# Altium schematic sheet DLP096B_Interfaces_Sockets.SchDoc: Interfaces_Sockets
size 431 x 279 mm; Date: Not shown in title block; ApprovedBy: Not shown in title block; CheckedBy: Not shown in title block; Author: Not shown in title block; CompanyName: Not shown in title block; Engineer: Not shown in title block; Organization: Not shown in title block; Address1: Not shown in title block; Address2: Not shown in title block; Address3: Not shown in title block; Address4: Not shown in title block; DocumentNumber: 8; Revision: Use project parameter SCH_Rev; SheetNumber: 8; SheetTotal: 10; PageSetup: Record=PageOptions¦CenterHorizontal=True¦CenterVertical=True¦PrintScale=1.00¦XCorrection=1.00¦YCorrection=1.00¦PrintKind=0¦BorderSize=5000000¦LeftOffset=0¦BottomOffset=0¦Orientation=2¦PaperLength=1000¦PaperWidth=1000¦Scale=100¦PaperSource=15¦PrintQuality=600¦MediaType=1¦DitherType=10¦PaperKind=Letter¦PrintScaleMode=1
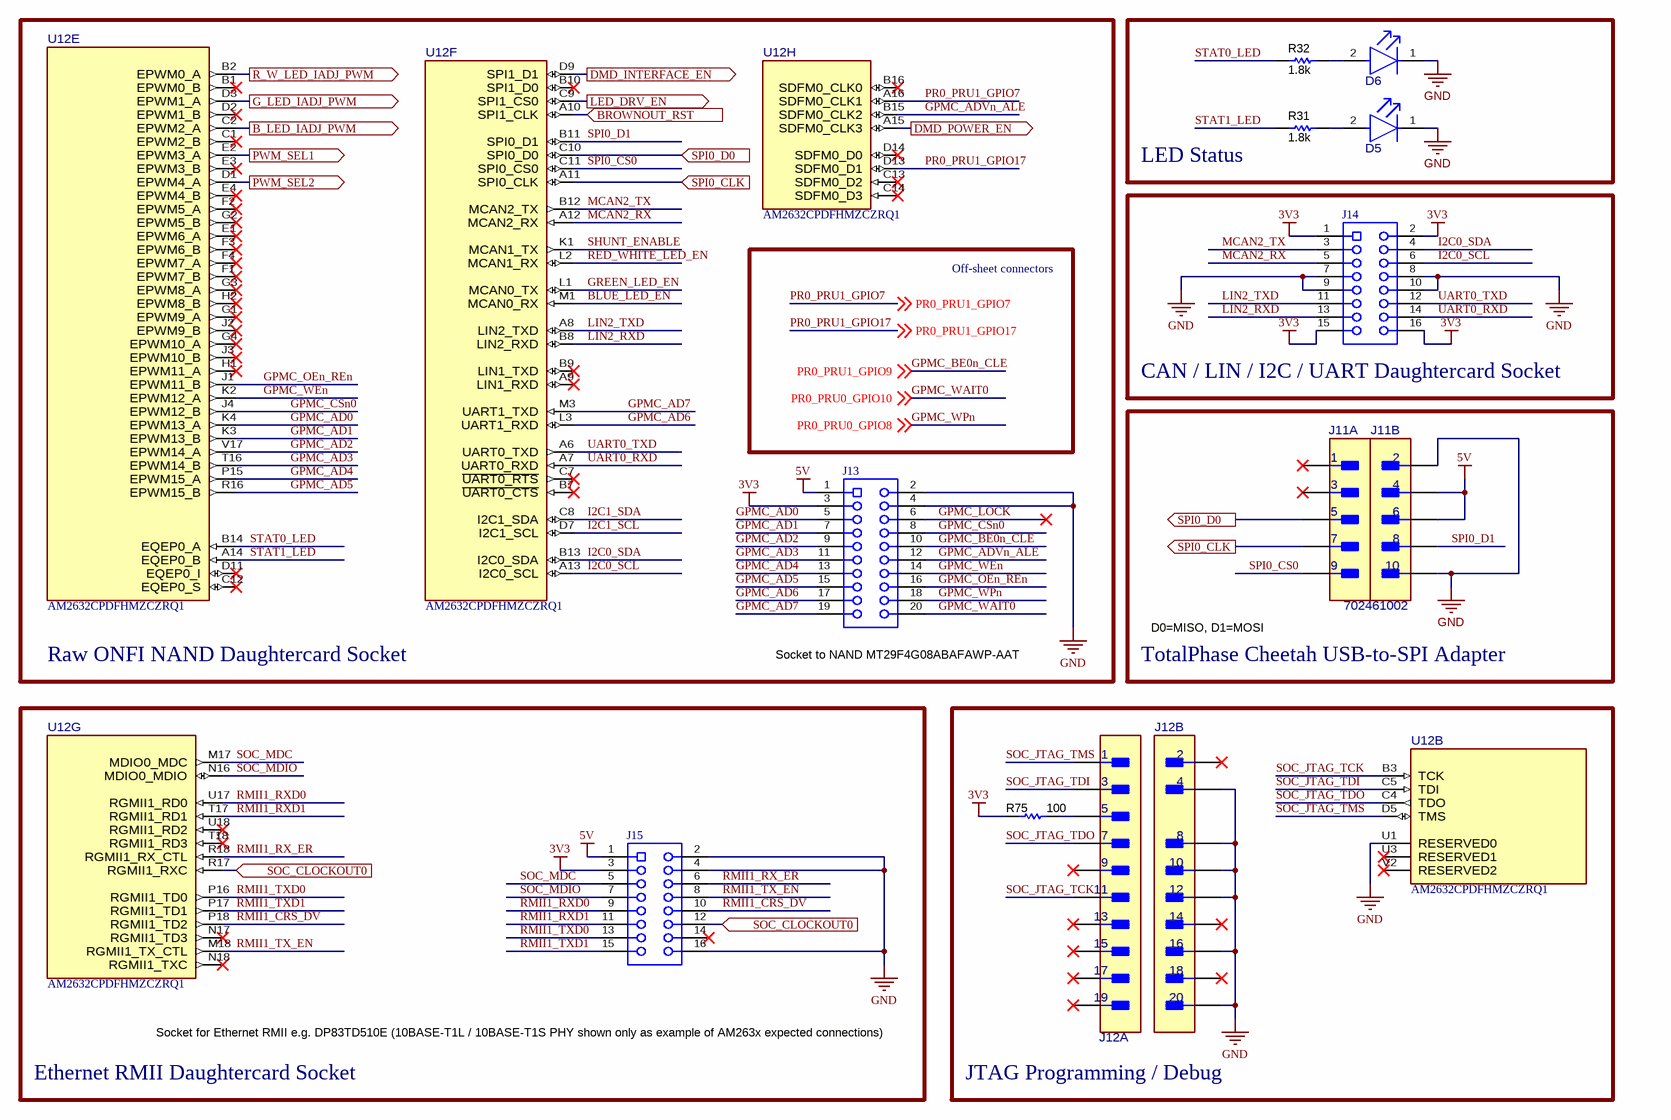
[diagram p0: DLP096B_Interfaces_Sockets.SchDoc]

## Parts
D5  LSL29K-G1H2-1-Z  [FP-LSL29K-G1H2-1-Z_0603-0]  (value not drawn)
D6  LSL29K-G1H2-1-Z  [FP-LSL29K-G1H2-1-Z_0603-0]  (value not drawn)
J11  702461002  [FP-702461002_HDR10-MFG]  (value not drawn)  (parts A,B of 2)
J12  FTR-110-03-G-D-06  [FP-FTR-110-03-G-D-06_HDR19-MFG]  (value not drawn)  (parts A,B of 2)
J13  RSM-110-02-L-D  [Samtec_RSM-110-02-x-D]  (value not drawn)
J14  FLE-108-01-G-DV-A  [Samtec_FLE-108-01-x-DV-A]  (value not drawn)
J15  FLE-108-01-G-DV-A  [Samtec_FLE-108-01-x-DV-A]  (value not drawn)
R31  ValueDisplayed: 1.8k  [0402L]  (hidden comment: CRCW04021K80JNED)
R32  ValueDisplayed: 1.8k  [0402L]  (hidden comment: CRCW04021K80JNED)
R75  ValueDisplayed: 100  [0402L]  (hidden comment: ERJ-2GEJ101X)
U12  PartNumber: AM2632CPDFHMZCZRQ1  [ZCZ0324A-MFG]  (hidden comment: XAM2634AOLFGMZCZQ)  (parts B,E,F,G,H of 13)

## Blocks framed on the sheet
Raw ONFI NAND Daughtercard Socket: J13 U12
LED Status: D5 D6 R31 R32
CAN / LIN / I2C / UART Daughtercard Socket: J14
TotalPhase Cheetah USB-to-SPI Adapter: J11
Ethernet RMII Daughtercard Socket: J15 U12
JTAG Programming / Debug: J12 R75 U12

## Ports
B_LED_IADJ_PWM (out), BROWNOUT_RST (in), DMD_INTERFACE_EN (out), DMD_POWER_EN (out), G_LED_IADJ_PWM (out), LED_DRV_EN (out), PWM_SEL1 (out), PWM_SEL2 (out), R_W_LED_IADJ_PWM (out), SOC_CLOCKOUT0 (in), SPI0_CLK (in), SPI0_CLK (out), SPI0_D0 (in), SPI0_D0 (out)

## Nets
3V3: J13.3 J14.1 J14.2 J14.15 J14.16 J15.3 R75.1
5V: J11.4 J11.6 J13.1 J15.1
GND: D5.1(CATHODE) D6.1(CATHODE) J11.2 J11.10 J12.4 J12.8 J12.10 J12.12 J12.16 J12.20 J13.2 J13.4 J14.7 J14.8 J14.9 J14.10 J15.2 J15.4 J15.16 U12.U1(RESERVED0)
B_LED_IADJ_PWM: U12.C2(EPWM2_A) ; port B_LED_IADJ_PWM
BLUE_LED_EN: U12.M1(MCAN0_RX)
BROWNOUT_RST: U12.A10(SPI1_CLK) ; port BROWNOUT_RST
DMD_INTERFACE_EN: U12.D9(SPI1_D1) ; port DMD_INTERFACE_EN
DMD_POWER_EN: U12.A15(SDFM0_CLK3) ; port DMD_POWER_EN
G_LED_IADJ_PWM: U12.D3(EPWM1_A) ; port G_LED_IADJ_PWM
GPMC_AD0: J13.5 U12.K4(EPWM13_A)
GPMC_AD1: J13.7 U12.K3(EPWM13_B)
GPMC_AD2: J13.9 U12.V17(EPWM14_A)
GPMC_AD3: J13.11 U12.T16(EPWM14_B)
GPMC_AD4: J13.13 U12.P15(EPWM15_A)
GPMC_AD5: J13.15 U12.R16(EPWM15_B)
GPMC_AD6: J13.17 U12.L3(UART1_RXD)
GPMC_AD7: J13.19 U12.M3(UART1_TXD)
GPMC_ADVn_ALE: J13.12 U12.B15(SDFM0_CLK2)
GPMC_BE0n_CLE: J13.10 ; off-sheet PR0_PRU1_GPIO9  [also labelled PR0_PRU1_GPIO9]
GPMC_CSn0: J13.8 U12.J4(EPWM12_B)
GPMC_LOCK: J13.6
GPMC_OEn_REn: J13.16 U12.J1(EPWM11_B)
GPMC_WAIT0: J13.20 ; off-sheet PR0_PRU0_GPIO10  [also labelled PR0_PRU0_GPIO10]
GPMC_WEn: J13.14 U12.K2(EPWM12_A)
GPMC_WPn: J13.18 ; off-sheet PR0_PRU0_GPIO8  [also labelled PR0_PRU0_GPIO8]
GREEN_LED_EN: U12.L1(MCAN0_TX)
I2C0_SCL: J14.6 U12.A13(I2C0_SCL)
I2C0_SDA: J14.4 U12.B13(I2C0_SDA)
I2C1_SCL: U12.D7(I2C1_SCL)
I2C1_SDA: U12.C8(I2C1_SDA)
LED_DRV_EN: U12.C9(SPI1_CS0) ; port LED_DRV_EN
LIN2_RXD: J14.13 U12.B8(LIN2_RXD)
LIN2_TXD: J14.11 U12.A8(LIN2_TXD)
MCAN2_RX: J14.5 U12.A12(MCAN2_RX)
MCAN2_TX: J14.3 U12.B12(MCAN2_TX)
PR0_PRU1_GPIO7: U12.A16(SDFM0_CLK1) ; off-sheet PR0_PRU1_GPIO7
PR0_PRU1_GPIO17: U12.D13(SDFM0_D1) ; off-sheet PR0_PRU1_GPIO17
PWM_SEL1: U12.E2(EPWM3_A) ; port PWM_SEL1
PWM_SEL2: U12.D1(EPWM4_A) ; port PWM_SEL2
R_W_LED_IADJ_PWM: U12.B2(EPWM0_A) ; port R_W_LED_IADJ_PWM
RED_WHITE_LED_EN: U12.L2(MCAN1_RX)
RMII1_CRS_DV: J15.10 U12.P18(RGMII1_TD2)
RMII1_RX_ER: J15.6 U12.R18(RGMII1_RX_CTL)
RMII1_RXD0: J15.9 U12.U17(RGMII1_RD0)
RMII1_RXD1: J15.11 U12.T17(RGMII1_RD1)
RMII1_TX_EN: J15.8 U12.M18(RGMII1_TX_CTL)
RMII1_TXD0: J15.13 U12.P16(RGMII1_TD0)
RMII1_TXD1: J15.15 U12.P17(RGMII1_TD1)
SHUNT_ENABLE: U12.K1(MCAN1_TX)
SOC_CLOCKOUT0: J15.12 U12.R17(RGMII1_RXC) ; port SOC_CLOCKOUT0
SOC_JTAG_TCK: J12.11 U12.B3(TCK)
SOC_JTAG_TDI: J12.3 U12.C5(TDI)
SOC_JTAG_TDO: J12.7 U12.C4(TDO)
SOC_JTAG_TMS: J12.1 U12.D5(TMS)
SOC_MDC: J15.5 U12.M17(MDIO0_MDC)
SOC_MDIO: J15.7 U12.N16(MDIO0_MDIO)
SPI0_CLK: J11.7 U12.A11(SPI0_CLK) ; port SPI0_CLK
SPI0_CS0: J11.9 U12.C11(SPI0_CS0)
SPI0_D0: J11.5 U12.C10(SPI0_D0) ; port SPI0_D0
SPI0_D1: J11.8 U12.B11(SPI0_D1)
STAT0_LED: R32.2 U12.B14(EQEP0_A)
STAT1_LED: R31.2 U12.A14(EQEP0_B)
UART0_RXD: J14.14 U12.A7(UART0_RXD)
UART0_TXD: J14.12 U12.A6(UART0_TXD)
NetD5_2: D5.2(ANODE) R31.1
NetD6_2: D6.2(ANODE) R32.1
NetJ12_5: J12.5 R75.2

Not connected (* = marked no-connect by the designer): J11 1* 3*; J12 2* 9* 13* 14* 15* 17* 18* 19*; J15 14*; U12 A9(LIN1_RXD)* B1(EPWM0_B)* B7(~{UART0_CTS})* B9(LIN1_TXD)* B10(SPI1_D0)* B16(SDFM0_CLK0)* C1(EPWM2_B)* C7(~{UART0_RTS})* C12(EQEP0_S)* C13(SDFM0_D2)* C14(SDFM0_D3)* D2(EPWM1_B)* D11(EQEP0_I)* D14(SDFM0_D0)* E1(EPWM6_A)* E3(EPWM3_B)* E4(EPWM4_B)* F1(EPWM7_B)* F2(EPWM5_A)* F3(EPWM6_B)* F4(EPWM7_A)* G1(EPWM9_A)* G2(EPWM5_B)* G3(EPWM8_A)* G4(EPWM10_A)* H1(EPWM11_A)* H2(EPWM8_B)* J2(EPWM9_B)* J3(EPWM10_B)* N17(RGMII1_TD3)* N18(RGMII1_TXC)* T18(RGMII1_RD3)* U3(RESERVED1)* U18(RGMII1_RD2)* V2(RESERVED2)*

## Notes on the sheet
- Off-sheet connectors
- (near J13) Socket to NAND MT29F4G08ABAFAWP-AAT
- D0=MISO, D1=MOSI
- Socket for Ethernet RMII e.g. DP83TD510E (10BASE-T1L / 10BASE-T1S PHY shown only as example of AM263x expected connections)

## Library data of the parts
D5 D6 = CMP-0092845-1: LED Uni-Color Red 643nm 2-Pin Chip 0603(1608Metric) T/R; Manufacturer: OSRAM Opto Semiconductors; AEC Grade: Grade 2; LuminousFlux_PhiV: 8.1/16.1lm; Vf_V: 1.8V; Forward Current: 2mA; Led Orientation: Top View; SizeZ_mm: 0.67mm; AEC Qualified: Yes; Luminous Intensity: 1.8-2.24/3.55-4.5mcd; Vr_V: 12V; Angle: 160°; LambdaD: 630nm; Tjmax_C: 110°C
J11 = CMP-0089821-1: Connector Header Through Hole 10 position 0.100" (2.54mm); Manufacturer: Molex; Voltage_V: 250V; Conn Gender: Male; SizeZ_mm: 9.47mm; Standoff Height: 0.38mm; Row_Count: 2; Conn Orientation: Vertical; AEC Qualified: No; ContactFinish: Gold,Nickel; Current_A: 2.5A
J12 = CMP-0092119-1: Connector Header Surface Mount 20 position 0.050" (1.27mm); Manufacturer: Samtec; ContactFinish: Gold; Standoff Height: 1mm; Row_Count: 2; AEC Qualified: No; Conn Orientation: Vertical; Current_A: 3.1A; Conn Gender: Male; SizeZ_mm: 7.58mm
J13 = CMP-0081743-1: Receptacle, 1.27mm, 10x2, Gold with Tin tail, SMT; Manufacturer: Samtec; Pitch_mm: 1.27; Gender: Female; Cert_UL: Y; Current_A: 3.1A; RowSpacing_mm: 2.54; Row_Count: 2; CompType: Socket Strip
J14 J15 = CMP-0077240-1: Receptacle, 1.27mm, 8x2, Gold, SMT; Manufacturer: Samtec; Pitch_mm: 1.27; Gender: Female; Cert_CSA: Y; Current_A: 2A; CT: True; Row_Count: 2; CompType: Socket Strip; CNHeader: False
R31 R32 = CMP-0026858-5: RES, 1.8 k, 5%, 0.063 W, AEC-Q200 Grade 0, 0402; Manufacturer: Vishay-Dale; Power_W: 63mW; TempCo: 200 ppm/C; Value_Code: 1k80; Value: 1.8k; EIA_Code: E24; SizeX_mm: 1; SizeY_mm: 0.5; SizeZ_mm: 0.6; Value2: 0.063W; AEC Qualified: Y; VDC_V: 50V; AEC Category: Q200; AEC Grade: 0
R75 = CMP-0026993-2: RES, 100, 5%, 0.1 W, AEC-Q200 Grade 0, 0402; Manufacturer: Panasonic; Power_W: 100mW; TempCo: 200 ppm/C; Value_Code: 100R; U/M: EA; Value: 100; EIA_Code: E24; SizeX_mm: 1; SizeY_mm: 0.5; SizeZ_mm: 0.6; Value2: 0.1W; AEC Qualified: Y; AEC Grade: 0; AEC Category: Q200
U12 = CMP-0093674-1: Sitara™ Microcontrollers; Manufacturer: Texas Instruments; Min Supply Voltage: 1.14V; Number Of Adc Channels: 30; AEC Qualified: No; TJmax_C: +105°C; Memory Type: SRAM; Standoff Height: 0.35mm; Core Architecture: ARM Cortex-R5F; Number Of I2C Channels: 4; Number Of Pwm Channels: 24; Number Of Spi Channels: 5; Number Of Cores: 2; Frequency_Fixed: 400MHz; Nominal Supply Current: 200-2500mA; Ram Size: 2MBytes; Number Of Ethernet Channels: 1; Interface: I2C,SPI,UART,CAN,LIN,Ethernet,Other; Data Bus Width: 64bits; SizeZ_mm: 1.4mm; Number Of Uart Channels: 6; Number Of I/Os: 140; Max Supply Voltage: 3.465V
